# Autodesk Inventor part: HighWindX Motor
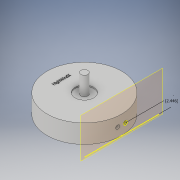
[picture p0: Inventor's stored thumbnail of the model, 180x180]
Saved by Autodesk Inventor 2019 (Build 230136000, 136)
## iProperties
Created: 2018-12
Part Number: HighWindX Motor
Material: Generic
Document SubType Name: Modeling
Designer: Patel Family
Density: 1 g/cm^3
Appearance: Default
Author: Patel Family
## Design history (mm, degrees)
sketch "Sketch1"
  geometry: C1 r 10 at (0, 0); 1 further point
  constraints: 1 centre point, 1 coincident
  dimensions: "d0" = 20 diameter of C1
extrude "Extrusion1" new body sketch "Sketch1" distance "d1" = 5; taper "d2" = 0 deg
sketch "Sketch2"
  geometry: C1 r 2.5 at (0, 0); 1 further point
  constraints: 1 centre point, 1 coincident
  dimensions: "d3" = 5 diameter of C1
extrude "Extrusion2" cut sketch "Sketch2" distance "d4" = 0.3; taper "d5" = 0 deg
sketch "Sketch3"
  geometry: C1 r 0.95 at (0, 0); 1 further point
  constraints: 1 centre point, 1 coincident
  dimensions: "d6" = 1.9 diameter of C1
extrude "Extrusion3" join sketch "Sketch3" distance "d7" = 5; taper "d8" = 0 deg
sketch "Sketch4"
  geometry: L1 (-6.493, -2.405)-(-6.493, 2.25); L2 (-6.493, 2.25)-(-5.563, 2.25); L3 (-5.563, 2.25)-(-5.563, -2.405); L4 (-5.563, -2.405)-(-6.493, -2.405); 1 further point
  constraints: 2 other
emboss "Emboss1" sketch "Sketch4" dims "d9" = 0.5, "d10" = 0
sketch "Sketch5"
  geometry: 1 further point
sketch "Sketch6"
  geometry: 1 further point
workplane "Work Plane1"
sketch "Sketch7"
  geometry: L1 (2.446, 0)-(2.446, -1); L2 (2.446, -1)-(2.446, 1); C1 r 0.6 at (2.446, -1); C2 r 0.6 at (2.446, 1); 1 further point
  constraints: 4 end point, 2 centre point, 2 coincident, 1 point on line, 1 vertical
  dimensions: "d12" = 1 distance of L1.start L1.end; "d13" = 2 distance of L1.end L2.end; "d14" = 1.2 diameter of C1; "d15" = 1.2 diameter of C2
hole "Hole1" sketch "Sketch7" at (2.446, -1), (2.446, 1) diameter "d16" = 1; stored, may be unused: countersink angle "d20" = 90 deg, drill point angle "d22" = 118 deg; dims "d17" = 6, "d18" = 4, "d19" = 2, "d21" = 2
sketch "Sketch8"
  geometry: 1 further point
sketch "Sketch9"
  geometry: L1 (0, 10)-(0, -10) reference; C1 r 0.5 at (2.446, -1) reference; 1 further point
  dimensions: "d23" = 2.44619 distance from line of L1 C1.centre (derived)
body "Solid1"
